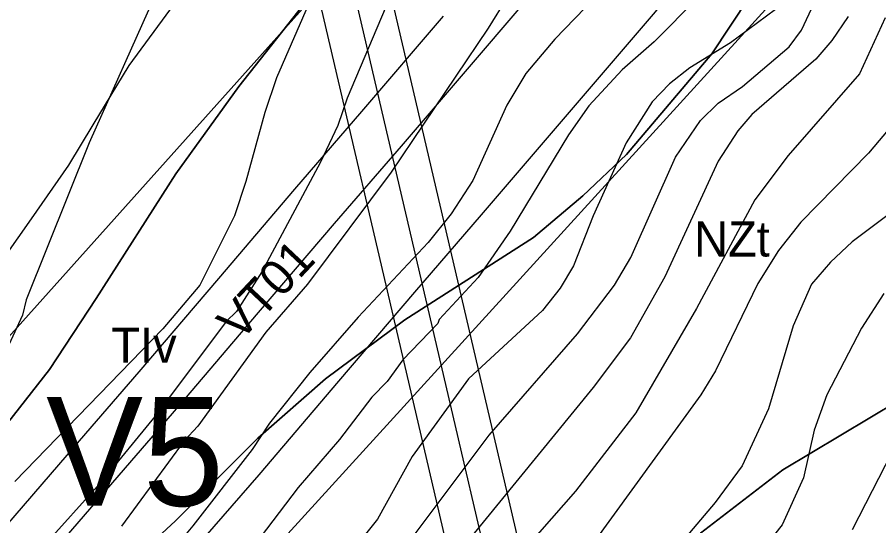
# Model space of a CAD drawing. Extents: x -758499 to -754160, y -1175205 to -1172032.
# Drawn here: x -755607.2 to -755362.3, y -1173797.8 to -1173653.3 of the extents above; entities that cross this region are included whole.
import ezdxf

# ---------------------------------------------------------------- set-up
doc = ezdxf.new("R2010")
doc.units = 0
for name, color, linetype in [('A041_BPEJ_p', 7, 'Continuous'), ('A068_Vodovod_l', 7, 'Continuous'), ('A073_ElVed_l_VN', 7, 'Continuous'), ('A073_ElVed_op', 7, 'Continuous'), ('A118_ZamZUR_TI_p', 7, 'Continuous'), ('indexy RZV_TYP_1', 7, 'Continuous'), ('indexy RZV_TYP_2', 7, 'Continuous'), ('LIMITY OP vodovodu', 7, 'Continuous'), ('PLOCHY NZo zemědělské-orná půda', 7, 'Continuous'), ('PLOCHY NZt zeměděl-trvalý travní porost', 7, 'Continuous'), ('Vk Vodovod koridor přivaděče', 7, 'Continuous'), ('VPS VODA popis', 7, 'Continuous'), ('VPS VODA- plochy a koridory', 7, 'Continuous'), ('vrstevnice', 7, 'Continuous')]:
    doc.layers.add(name, color=color, linetype=linetype)

msp = doc.modelspace()

# ---------------------------------------------------------------- linework, layer by layer
at = {"layer": 'A041_BPEJ_p'}
for p, q in [((-755384.08, -1173624.9), (-755409.73, -1173663.68)), ((-755409.73, -1173663.68), (-755384.08, -1173624.9)), ((-755516.01, -1173637.16), (-755544.19, -1173672.96)), ((-755544.19, -1173672.96), (-755516.01, -1173637.16)), ((-755409.73, -1173663.68), (-755434.05, -1173692.31)), ((-755434.05, -1173692.31), (-755409.73, -1173663.68)), ((-755544.19, -1173672.96), (-755562.13, -1173697.82)), ((-755562.13, -1173697.82), (-755544.19, -1173672.96)), ((-755434.05, -1173692.31), (-755446.41, -1173704.09)), ((-755446.41, -1173704.09), (-755434.05, -1173692.31)), ((-755562.13, -1173697.82), (-755584.79, -1173733.23)), ((-755584.79, -1173733.23), (-755562.13, -1173697.82)), ((-755446.41, -1173704.09), (-755460.46, -1173715.85)), ((-755460.46, -1173715.85), (-755446.41, -1173704.09)), ((-755460.46, -1173715.85), (-755497.05, -1173739.31)), ((-755497.05, -1173739.31), (-755460.46, -1173715.85)), ((-755584.79, -1173733.23), (-755598.04, -1173753.46)), ((-755598.04, -1173753.46), (-755584.79, -1173733.23)), ((-755497.05, -1173739.31), (-755519.61, -1173756.1)), ((-755519.61, -1173756.1), (-755497.05, -1173739.31)), ((-755389.58, -1173781.94), (-755330.88, -1173746.76)), ((-755330.88, -1173746.76), (-755389.58, -1173781.94)), ((-755598.04, -1173753.46), (-755609.99, -1173768.63)), ((-755609.99, -1173768.63), (-755598.04, -1173753.46)), ((-755519.61, -1173756.1), (-755538.78, -1173772.91)), ((-755538.78, -1173772.91), (-755519.61, -1173756.1)), ((-755538.78, -1173772.91), (-755562.23, -1173796.46)), ((-755562.23, -1173796.46), (-755538.78, -1173772.91)), ((-755412.99, -1173799.99), (-755389.58, -1173781.94)), ((-755389.58, -1173781.94), (-755412.99, -1173799.99)), ((-755562.23, -1173796.46), (-755600.58, -1173831.77)), ((-755600.58, -1173831.77), (-755562.23, -1173796.46))]:
    msp.add_line(p, q, dxfattribs=at)
at = {"layer": 'A068_Vodovod_l'}
for p, q in [((-755474.71, -1173662.76), (-755450.32, -1173634.24)), ((-755498.02, -1173689.9), (-755474.71, -1173662.76)), ((-755516.99, -1173711.92), (-755498.02, -1173689.9)), ((-755538.63, -1173737.26), (-755516.99, -1173711.92)), ((-755561.25, -1173763.81), (-755538.63, -1173737.26)), ((-755576.44, -1173781.4), (-755561.25, -1173763.81)), ((-755606.69, -1173816.4), (-755576.44, -1173781.4))]:
    msp.add_line(p, q, dxfattribs=at)
at = {"layer": 'A073_ElVed_l_VN'}
msp.add_lwpolyline([(-755471.11, -1172485.19), (-755484.36, -1172568.86), (-755498.88, -1172660.64), (-755513.21, -1172750.36), (-755527.07, -1172837.72), (-755540.95, -1172925.03), (-755554.97, -1173012.79), (-755568.83, -1173101.8), (-755583.06, -1173190.56), (-755596.96, -1173277.28), (-755579.85, -1173351.69), (-755557.11, -1173449.7), (-755535.13, -1173543.9), (-755513.23, -1173638.68), (-755485.47, -1173757.64), (-755457.99, -1173875.52), (-755516.92, -1174007.51), (-755573.12, -1174132.37), (-755576.12, -1174278.08), (-755556.69, -1174326.93), (-755536.35, -1174378.48), (-755490.83, -1174493.14)], dxfattribs=at)
at = {"layer": 'A073_ElVed_op'}
for points in [[(-755499.43, -1174498.59), (-755545.65, -1174382.16), (-755565.99, -1174330.61), (-755586.16, -1174279.9), (-755583.08, -1174130.13), (-755526.05, -1174003.42), (-755468.49, -1173874.51), (-755495.21, -1173759.91), (-755522.97, -1173640.94), (-755544.87, -1173546.16), (-755566.85, -1173451.97), (-755589.59, -1173353.94), (-755607.14, -1173277.62), (-755578.71, -1173100.24), (-755564.85, -1173011.23), (-755550.83, -1172923.46), (-755536.95, -1172836.15), (-755523.09, -1172748.79), (-755508.76, -1172659.07), (-755494.24, -1172567.3), (-755481.8, -1172488.78)], [(-755466.38, -1172519.27), (-755474.48, -1172570.42), (-755489, -1172662.21), (-755503.33, -1172751.93), (-755517.19, -1172839.29), (-755531.07, -1172926.6), (-755545.09, -1173014.35), (-755558.95, -1173103.36), (-755586.78, -1173276.94), (-755570.11, -1173349.44), (-755547.37, -1173447.43), (-755525.39, -1173541.64), (-755503.49, -1173636.42), (-755475.73, -1173755.37), (-755447.49, -1173876.53), (-755507.79, -1174011.6), (-755563.16, -1174134.61), (-755566.08, -1174276.26), (-755547.39, -1174323.25), (-755527.05, -1174374.8), (-755482.23, -1174487.69)]]:
    msp.add_lwpolyline(points, dxfattribs=at)
at = {"layer": 'LIMITY OP vodovodu'}
for points in [[(-755699.04, -1173969.84), (-755681.14, -1173949.22), (-755668.84, -1173934.71), (-755653.87, -1173917.02), (-755628.94, -1173888.16), (-755607.01, -1173862.66), (-755583.99, -1173836.01), (-755553.74, -1173801.01), (-755538.48, -1173783.34), (-755515.81, -1173756.73), (-755494.22, -1173731.45), (-755475.28, -1173709.46), (-755451.93, -1173682.28), (-755427.49, -1173653.71), (-755407.7, -1173630.43), (-755392.45, -1173612.66), (-755382.31, -1173600.5), (-755367.02, -1173582.12), (-755363.97, -1173578.13), (-755362.25, -1173575.55)], [(-755486.1, -1173653), (-755509.39, -1173680.12), (-755528.38, -1173702.15), (-755550.04, -1173727.53), (-755572.64, -1173754.04), (-755587.79, -1173771.59), (-755618.04, -1173806.59), (-755641.09, -1173833.28), (-755663.02, -1173858.78), (-755688.07, -1173887.77), (-755703.18, -1173905.63), (-755715.3, -1173919.92), (-755728.83, -1173935.52), (-755737.48, -1173945.22), (-755739.9, -1173947.78), (-755741.42, -1173949.74), (-755742.47, -1173951.35)]]:
    msp.add_lwpolyline(points, dxfattribs=at)
at = {"layer": 'PLOCHY NZo zemědělské-orná půda'}
msp.add_lwpolyline([(-755774.47, -1173746.69), (-755731.74, -1173755.32), (-755711.52, -1173760.8), (-755708.16, -1173761.85), (-755695.86, -1173764), (-755683.47, -1173768.97), (-755652.77, -1173779.58), (-755638.56, -1173760.23), (-755623.48, -1173739.45), (-755603.19, -1173710.56), (-755592.51, -1173695.34), (-755585.59, -1173683.91), (-755575.37, -1173667.04), (-755553.02, -1173636.46), (-755540.75, -1173619.31), (-755531.34, -1173605.45), (-755510.14, -1173574.21), (-755503.42, -1173564.3), (-755467.26, -1173503.89), (-755523.24, -1173488.69)], dxfattribs=at)
at = {"layer": 'PLOCHY NZt zeměděl-trvalý travní porost'}
msp.add_lwpolyline([(-755757.69, -1173899.73), (-755747.02, -1173887.47), (-755742.25, -1173881.98), (-755731.55, -1173871.43), (-755720.4, -1173860.5), (-755695.68, -1173836.28), (-755672.52, -1173813.36), (-755654.05, -1173790.64), (-755646.94, -1173781.89), (-755652.77, -1173779.58), (-755638.56, -1173760.23), (-755623.48, -1173739.45), (-755603.19, -1173710.56), (-755592.51, -1173695.34), (-755585.59, -1173683.91), (-755575.37, -1173667.04), (-755553.02, -1173636.46)], dxfattribs=at)
at = {"layer": 'Vk Vodovod koridor přivaděče'}
msp.add_lwpolyline([(-755745.4, -1173964.02), (-755747.04, -1173909.62), (-755734.63, -1173883.68), (-755408.58, -1173519.49), (-755395.42, -1173522.98), (-755331.32, -1173539.23), (-755302.4, -1173549.9), (-755612.78, -1173890.64), (-755650.37, -1173938.75), (-755664.46, -1173962.64)], dxfattribs=at)
at = {"layer": 'VPS VODA- plochy a koridory'}
msp.add_lwpolyline([(-755745.4, -1173964.02), (-755747.04, -1173909.62), (-755734.63, -1173883.68), (-755408.58, -1173519.49), (-755395.42, -1173522.98), (-755331.32, -1173539.23), (-755302.4, -1173549.9), (-755612.78, -1173890.64), (-755650.37, -1173938.75), (-755664.46, -1173962.64)], dxfattribs=at)
at = {"layer": 'vrstevnice'}
for p, q in [((-755460.49, -1173635.6), (-755473.33, -1173656.38)), ((-755460.49, -1173635.6), (-755473.33, -1173656.38)), ((-755563.82, -1173637.62), (-755586.77, -1173689)), ((-755563.82, -1173637.62), (-755586.77, -1173689)), ((-755498.01, -1173639.93), (-755513.46, -1173676.3)), ((-755498.01, -1173639.93), (-755513.46, -1173676.3)), ((-755435.81, -1173640.22), (-755454.43, -1173659.56)), ((-755435.81, -1173640.22), (-755454.43, -1173659.56)), ((-755384.29, -1173656.96), (-755378.22, -1173643.97)), ((-755384.29, -1173656.96), (-755378.22, -1173643.97)), ((-755522.84, -1173645.99), (-755533.52, -1173670.53)), ((-755412.43, -1173646.43), (-755426.14, -1173660.28)), ((-755412.43, -1173646.43), (-755426.14, -1173660.28)), ((-755391.65, -1173651.04), (-755404.49, -1173660.57)), ((-755371.01, -1173653.06), (-755375.63, -1173659.85)), ((-755371.01, -1173653.06), (-755375.63, -1173659.85)), ((-755360.47, -1173653.5), (-755367.83, -1173669.37)), ((-755360.47, -1173653.5), (-755367.83, -1173669.37)), ((-755473.33, -1173656.38), (-755500.9, -1173697.37)), ((-755473.33, -1173656.38), (-755500.9, -1173697.37)), ((-755387.75, -1173661.72), (-755384.29, -1173656.96)), ((-755387.75, -1173661.72), (-755384.29, -1173656.96)), ((-755454.43, -1173659.56), (-755462.65, -1173669.23)), ((-755454.43, -1173659.56), (-755462.65, -1173669.23)), ((-755426.14, -1173660.28), (-755435.23, -1173668.22)), ((-755426.14, -1173660.28), (-755435.23, -1173668.22)), ((-755375.63, -1173659.85), (-755380.24, -1173665.19)), ((-755375.63, -1173659.85), (-755380.24, -1173665.19)), ((-755404.49, -1173660.57), (-755416.04, -1173667.64)), ((-755401.03, -1173672.98), (-755387.75, -1173661.72)), ((-755401.03, -1173672.98), (-755387.75, -1173661.72)), ((-755380.24, -1173665.19), (-755398.43, -1173680.92)), ((-755380.24, -1173665.19), (-755398.43, -1173680.92)), ((-755416.04, -1173667.64), (-755421.81, -1173672.26)), ((-755462.65, -1173669.23), (-755467.99, -1173678.32)), ((-755462.65, -1173669.23), (-755467.99, -1173678.32)), ((-755435.23, -1173668.22), (-755444.76, -1173678.47)), ((-755435.23, -1173668.22), (-755444.76, -1173678.47)), ((-755367.83, -1173669.37), (-755388.04, -1173692.61)), ((-755367.83, -1173669.37), (-755388.04, -1173692.61)), ((-755533.52, -1173670.53), (-755536.84, -1173680.34)), ((-755421.81, -1173672.26), (-755426.72, -1173677.31)), ((-755407.96, -1173677.74), (-755401.03, -1173672.98)), ((-755407.96, -1173677.74), (-755401.03, -1173672.98)), ((-755513.46, -1173676.3), (-755516.05, -1173684.09)), ((-755513.46, -1173676.3), (-755516.05, -1173684.09)), ((-755426.72, -1173677.31), (-755434.08, -1173689)), ((-755467.99, -1173678.32), (-755477.66, -1173699.68)), ((-755467.99, -1173678.32), (-755477.66, -1173699.68)), ((-755444.76, -1173678.47), (-755450.53, -1173686.69)), ((-755444.76, -1173678.47), (-755450.53, -1173686.69)), ((-755413.01, -1173682.65), (-755407.96, -1173677.74)), ((-755413.01, -1173682.65), (-755407.96, -1173677.74)), ((-755536.84, -1173680.34), (-755542.18, -1173699.97)), ((-755398.43, -1173680.92), (-755402.33, -1173685.54)), ((-755398.43, -1173680.92), (-755402.33, -1173685.54)), ((-755516.05, -1173684.09), (-755520.96, -1173694.49)), ((-755516.05, -1173684.09), (-755520.96, -1173694.49)), ((-755420.08, -1173693.04), (-755413.01, -1173682.65)), ((-755420.08, -1173693.04), (-755413.01, -1173682.65)), ((-755358.16, -1173683.52), (-755365.24, -1173691.89)), ((-755358.16, -1173683.52), (-755365.24, -1173691.89)), ((-755450.53, -1173686.69), (-755467.13, -1173714.11)), ((-755450.53, -1173686.69), (-755467.13, -1173714.11)), ((-755402.33, -1173685.54), (-755407.96, -1173694.2)), ((-755402.33, -1173685.54), (-755407.96, -1173694.2)), ((-755586.77, -1173689), (-755604.67, -1173733.6)), ((-755586.77, -1173689), (-755604.67, -1173733.6)), ((-755434.08, -1173689), (-755443.46, -1173709.78)), ((-755365.24, -1173691.89), (-755384.43, -1173711.52)), ((-755365.24, -1173691.89), (-755384.43, -1173711.52)), ((-755520.96, -1173694.49), (-755537.7, -1173725.66)), ((-755520.96, -1173694.49), (-755537.7, -1173725.66)), ((-755432.78, -1173721.62), (-755420.08, -1173693.04)), ((-755432.78, -1173721.62), (-755420.08, -1173693.04)), ((-755407.96, -1173694.2), (-755423.11, -1173727.1)), ((-755407.96, -1173694.2), (-755423.11, -1173727.1)), ((-755388.04, -1173692.61), (-755397.56, -1173705.17)), ((-755388.04, -1173692.61), (-755397.56, -1173705.17)), ((-755500.9, -1173697.37), (-755524.71, -1173729.12)), ((-755500.9, -1173697.37), (-755524.71, -1173729.12)), ((-755477.66, -1173699.68), (-755483.87, -1173709.21)), ((-755477.66, -1173699.68), (-755483.87, -1173709.21)), ((-755542.18, -1173699.97), (-755545.49, -1173709.78)), ((-755347.92, -1173700.55), (-755369.85, -1173717.14)), ((-755397.56, -1173705.17), (-755414.16, -1173736.05)), ((-755397.56, -1173705.17), (-755414.16, -1173736.05)), ((-755483.87, -1173709.21), (-755490.36, -1173717.29)), ((-755483.87, -1173709.21), (-755490.36, -1173717.29)), ((-755545.49, -1173709.78), (-755555.31, -1173729.41)), ((-755443.46, -1173709.78), (-755449.09, -1173723.93)), ((-755384.43, -1173711.52), (-755390.78, -1173719.6)), ((-755384.43, -1173711.52), (-755390.78, -1173719.6)), ((-755467.13, -1173714.11), (-755476.22, -1173727.25)), ((-755467.13, -1173714.11), (-755476.22, -1173727.25)), ((-755490.36, -1173717.29), (-755510.28, -1173738.5)), ((-755490.36, -1173717.29), (-755510.28, -1173738.5)), ((-755369.85, -1173717.14), (-755376.06, -1173722.92)), ((-755437.4, -1173729.41), (-755432.78, -1173721.62)), ((-755437.4, -1173729.41), (-755432.78, -1173721.62)), ((-755390.78, -1173719.6), (-755396.7, -1173728.98)), ((-755390.78, -1173719.6), (-755396.7, -1173728.98)), ((-755449.09, -1173723.93), (-755452.84, -1173730.28)), ((-755376.06, -1173722.92), (-755381.4, -1173729.12)), ((-755537.7, -1173725.66), (-755544.92, -1173736.92)), ((-755537.7, -1173725.66), (-755544.92, -1173736.92)), ((-755476.22, -1173727.25), (-755487.23, -1173739.24)), ((-755476.22, -1173727.25), (-755487.23, -1173739.24)), ((-755423.11, -1173727.1), (-755432.92, -1173744.42)), ((-755423.11, -1173727.1), (-755432.92, -1173744.42)), ((-755396.7, -1173728.98), (-755408.68, -1173753.8)), ((-755396.7, -1173728.98), (-755408.68, -1173753.8)), ((-755555.31, -1173729.41), (-755565.84, -1173741.82)), ((-755524.71, -1173729.12), (-755536.55, -1173742.83)), ((-755524.71, -1173729.12), (-755536.55, -1173742.83)), ((-755452.84, -1173730.28), (-755457.89, -1173736.63)), ((-755447.93, -1173743.27), (-755437.4, -1173729.41)), ((-755447.93, -1173743.27), (-755437.4, -1173729.41)), ((-755381.4, -1173729.12), (-755386.6, -1173740.96)), ((-755604.67, -1173733.6), (-755605.68, -1173737.93)), ((-755604.67, -1173733.6), (-755605.68, -1173737.93)), ((-755360.91, -1173731.86), (-755367.26, -1173741.68)), ((-755360.91, -1173731.86), (-755367.26, -1173741.68)), ((-755414.16, -1173736.05), (-755431.34, -1173765.78)), ((-755414.16, -1173736.05), (-755431.34, -1173765.78)), ((-755605.68, -1173737.93), (-755611.16, -1173749.91)), ((-755605.68, -1173737.93), (-755611.16, -1173749.91)), ((-755544.92, -1173736.92), (-755547.8, -1173739.8)), ((-755544.92, -1173736.92), (-755547.8, -1173739.8)), ((-755510.28, -1173738.5), (-755523.99, -1173754.23)), ((-755510.28, -1173738.5), (-755523.99, -1173754.23)), ((-755457.89, -1173736.63), (-755478.96, -1173756.11)), ((-755547.8, -1173739.8), (-755567.58, -1173766.21)), ((-755547.8, -1173739.8), (-755567.58, -1173766.21)), ((-755487.62, -1173740.38), (-755497.58, -1173750.63)), ((-755487.62, -1173740.38), (-755497.58, -1173750.63)), ((-755487.23, -1173739.24), (-755487.62, -1173740.38)), ((-755487.23, -1173739.24), (-755487.62, -1173740.38)), ((-755386.6, -1173740.96), (-755393.67, -1173764.63)), ((-755565.84, -1173741.82), (-755607.84, -1173785.26)), ((-755536.55, -1173742.83), (-755555.89, -1173769.53)), ((-755536.55, -1173742.83), (-755555.89, -1173769.53)), ((-755473.04, -1173772.13), (-755447.93, -1173743.27)), ((-755473.04, -1173772.13), (-755447.93, -1173743.27)), ((-755367.26, -1173741.68), (-755377.07, -1173760.59)), ((-755367.26, -1173741.68), (-755377.07, -1173760.59)), ((-755432.92, -1173744.42), (-755443.46, -1173758.56)), ((-755432.92, -1173744.42), (-755443.46, -1173758.56)), ((-755497.58, -1173750.63), (-755502.05, -1173756.83)), ((-755497.58, -1173750.63), (-755502.05, -1173756.83)), ((-755523.99, -1173754.23), (-755535.54, -1173768.67)), ((-755523.99, -1173754.23), (-755535.54, -1173768.67)), ((-755408.68, -1173753.8), (-755412.86, -1173760.59)), ((-755408.68, -1173753.8), (-755412.86, -1173760.59)), ((-755502.05, -1173756.83), (-755506.38, -1173761.31)), ((-755502.05, -1173756.83), (-755506.38, -1173761.31)), ((-755478.96, -1173756.11), (-755494.98, -1173778.19)), ((-755443.46, -1173758.56), (-755489.93, -1173815.28)), ((-755443.46, -1173758.56), (-755489.93, -1173815.28)), ((-755412.86, -1173760.59), (-755445.33, -1173805.18)), ((-755412.86, -1173760.59), (-755445.33, -1173805.18)), ((-755377.07, -1173760.59), (-755380.68, -1173770.69)), ((-755377.07, -1173760.59), (-755380.68, -1173770.69)), ((-755506.38, -1173761.31), (-755515.62, -1173773.29)), ((-755506.38, -1173761.31), (-755515.62, -1173773.29)), ((-755431.34, -1173765.78), (-755448.51, -1173788.01)), ((-755431.34, -1173765.78), (-755448.51, -1173788.01)), ((-755393.67, -1173764.63), (-755401.17, -1173780.79)), ((-755567.58, -1173766.21), (-755583.6, -1173785.7)), ((-755567.58, -1173766.21), (-755583.6, -1173785.7)), ((-755555.89, -1173769.53), (-755559.78, -1173773.72)), ((-755555.89, -1173769.53), (-755559.78, -1173773.72)), ((-755535.54, -1173768.67), (-755540.44, -1173776.17)), ((-755535.54, -1173768.67), (-755540.44, -1173776.17)), ((-755380.68, -1173770.69), (-755383.71, -1173784.25)), ((-755380.68, -1173770.69), (-755383.71, -1173784.25)), ((-755500.9, -1173809.08), (-755473.04, -1173772.13)), ((-755500.9, -1173809.08), (-755473.04, -1173772.13)), ((-755559.78, -1173773.72), (-755577.53, -1173797.97)), ((-755559.78, -1173773.72), (-755577.53, -1173797.97)), ((-755515.62, -1173773.29), (-755527.31, -1173787)), ((-755515.62, -1173773.29), (-755527.31, -1173787)), ((-755356.72, -1173773.29), (-755369.85, -1173798.98)), ((-755356.72, -1173773.29), (-755369.85, -1173798.98)), ((-755540.44, -1173776.17), (-755557.33, -1173797.82)), ((-755540.44, -1173776.17), (-755557.33, -1173797.82)), ((-755494.98, -1173778.19), (-755504.8, -1173795.94)), ((-755401.17, -1173780.79), (-755408.82, -1173791.18)), ((-755383.71, -1173784.25), (-755389.77, -1173797.53)), ((-755383.71, -1173784.25), (-755389.77, -1173797.53)), ((-755583.6, -1173785.7), (-755617.8, -1173823.65)), ((-755583.6, -1173785.7), (-755617.8, -1173823.65)), ((-755527.31, -1173787), (-755549.39, -1173815.86)), ((-755527.31, -1173787), (-755549.39, -1173815.86)), ((-755448.51, -1173788.01), (-755476.94, -1173820.19)), ((-755448.51, -1173788.01), (-755476.94, -1173820.19)), ((-755408.82, -1173791.18), (-755428.3, -1173814.27)), ((-755504.8, -1173795.94), (-755513.17, -1173806.34)), ((-755389.77, -1173797.53), (-755401.61, -1173812.54)), ((-755389.77, -1173797.53), (-755401.61, -1173812.54)), ((-755557.33, -1173797.82), (-755586.34, -1173833.18)), ((-755557.33, -1173797.82), (-755586.34, -1173833.18))]:
    msp.add_line(p, q, dxfattribs=at)

# ---------------------------------------------------------------- texts
at = {"layer": 'A118_ZamZUR_TI_p'}
msp.add_text('V5', height=30.878, dxfattribs=at).set_placement((-755598.98, -1173792.16))
at = {"layer": 'indexy RZV_TYP_1'}
msp.add_text('NZt', height=10, dxfattribs=at).set_placement((-755414.82, -1173721.31))
at = {"layer": 'indexy RZV_TYP_2'}
msp.add_text('TIv', height=10, dxfattribs=at).set_placement((-755580.46, -1173751.52))
at = {"layer": 'VPS VODA popis'}
msp.add_text('VT01', height=10, rotation=46.7098, dxfattribs=at).set_placement((-755543.91, -1173745.8))

doc.saveas('drawing.dxf')
